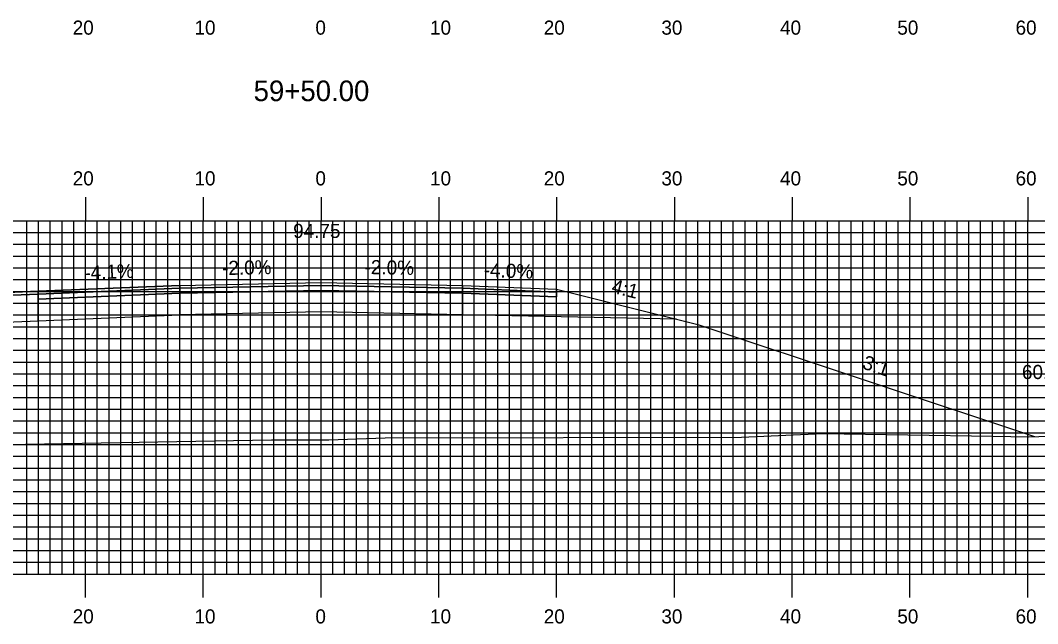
# Model space of a CAD drawing. Extents: x 1757462 to 1757806, y 442591 to 442811.
# Drawn here: x 1757602.6 to 1757689, y 442649.4 to 442700.7 of the extents above; entities that cross this region are included whole.
import ezdxf

# ---------------------------------------------------------------- set-up
doc = ezdxf.new("R2010")
doc.units = 0
for name, color, linetype in [('ANNOTATION', 7, 'Continuous'), ('D_Roadway_Centerline', 7, 'Continuous'), ('D_Roadway_Centerline_Text', 7, 'Continuous'), ('D_Roadway_Edge_Shoulder', 7, 'Continuous'), ('D_Roadway_Edge_TW', 7, 'Continuous'), ('D_Roadway_Pavement', 7, 'Continuous'), ('D_Roadway_SlopeLines', 7, 'Continuous'), ('D_Roadway_SubGrade', 7, 'Continuous'), ('D_Text_Standard', 7, 'Continuous'), ('H_V ANNOTATION', 7, 'Continuous'), ('MAJOR', 7, 'Continuous'), ('MINOR', 7, 'Continuous'), ('S_Roadway_Centerline', 7, 'Continuous')]:
    doc.layers.add(name, color=color, linetype=linetype)

msp = doc.modelspace()

# ---------------------------------------------------------------- linework, layer by layer
at = {"layer": 'D_Roadway_Centerline'}
msp.add_lwpolyline([(1757553.341, 442664.105), (1757577.567, 442672.184), (1757584.046, 442674.345), (1757584.056, 442674.348), (1757584.094, 442674.357), (1757595.268, 442677.152), (1757596.094, 442677.358), (1757604.094, 442677.678), (1757616.109, 442678.177), (1757628.109, 442678.417), (1757640.109, 442678.177), (1757648.109, 442677.857), (1757658.283, 442675.313), (1757660.109, 442674.857), (1757688.68, 442665.333)], dxfattribs=at)
at = {"layer": 'D_Roadway_Edge_Shoulder'}
for points in [[(1757604.094, 442677.678), (1757596.094, 442677.358), (1757596.094, 442677.108), (1757604.094, 442677.428)], [(1757640.109, 442678.177), (1757648.109, 442677.857), (1757648.109, 442677.607), (1757640.109, 442677.927)]]:
    msp.add_lwpolyline(points, close=True, dxfattribs=at)
at = {"layer": 'D_Roadway_Edge_TW'}
for points in [[(1757616.109, 442678.177), (1757604.094, 442677.678), (1757604.094, 442677.428), (1757616.109, 442677.927)], [(1757616.109, 442677.927), (1757616.109, 442678.177), (1757628.109, 442678.417), (1757640.109, 442678.177), (1757640.109, 442677.927), (1757628.109, 442678.167)]]:
    msp.add_lwpolyline(points, close=True, dxfattribs=at)
msp.add_lwpolyline([(1757616.109, 442678.177), (1757616.109, 442677.927)], dxfattribs=at)
at = {"layer": 'D_Roadway_Pavement'}
for points in [[(1757616.109, 442677.927), (1757604.094, 442677.428), (1757604.094, 442677.012), (1757616.109, 442677.51)], [(1757616.109, 442677.51), (1757616.109, 442677.927), (1757628.109, 442678.167), (1757640.109, 442677.927), (1757640.109, 442677.51), (1757628.109, 442677.75)], [(1757640.109, 442677.927), (1757648.109, 442677.607), (1757648.109, 442677.19), (1757640.109, 442677.51)]]:
    msp.add_lwpolyline(points, close=True, dxfattribs=at)
for points in [[(1757616.109, 442677.927), (1757616.109, 442677.51)], [(1757616.109, 442677.927), (1757616.109, 442677.51)], [(1757604.094, 442677.428), (1757604.094, 442677.012)]]:
    msp.add_lwpolyline(points, dxfattribs=at)
at = {"layer": 'D_Roadway_SlopeLines'}
msp.add_lwpolyline([(1757648.109, 442677.857), (1757660.109, 442674.857), (1757688.68, 442665.333)], dxfattribs=at)
at = {"layer": 'D_Roadway_SubGrade'}
for points in [[(1757616.109, 442675.677), (1757616.109, 442677.51), (1757628.109, 442677.75), (1757640.109, 442677.51), (1757640.109, 442675.677), (1757628.109, 442675.917)], [(1757640.109, 442677.51), (1757648.109, 442677.19), (1757648.109, 442677.607), (1757648.109, 442677.857), (1757658.283, 442675.313), (1757640.109, 442675.677)], [(1757604.094, 442677.012), (1757604.094, 442677.428), (1757596.094, 442677.108), (1757596.094, 442677.358), (1757584.046, 442674.345), (1757604.094, 442675.178)], [(1757616.109, 442677.51), (1757604.094, 442677.012), (1757604.094, 442675.178), (1757616.109, 442675.677)]]:
    msp.add_lwpolyline(points, close=True, dxfattribs=at)
msp.add_lwpolyline([(1757616.109, 442677.51), (1757616.109, 442675.677)], dxfattribs=at)
at = {"layer": 'MAJOR'}
for p, q in [((1757608.109, 442685.669), (1757608.109, 442683.665)), ((1757618.109, 442685.669), (1757618.109, 442683.665)), ((1757628.109, 442685.669), (1757628.109, 442683.665)), ((1757638.109, 442685.669), (1757638.109, 442683.665)), ((1757648.109, 442685.669), (1757648.109, 442683.665)), ((1757658.109, 442685.669), (1757658.109, 442683.665)), ((1757668.109, 442685.669), (1757668.109, 442683.665)), ((1757678.109, 442685.669), (1757678.109, 442683.665)), ((1757688.109, 442685.669), (1757688.109, 442683.665)), ((1757488.109, 442683.665), (1757768.109, 442683.665)), ((1757488.109, 442683.665), (1757768.109, 442683.665)), ((1757608.109, 442653.665), (1757608.109, 442683.665)), ((1757618.109, 442653.665), (1757618.109, 442683.665)), ((1757628.109, 442653.665), (1757628.109, 442683.665)), ((1757638.109, 442653.665), (1757638.109, 442683.665)), ((1757648.109, 442653.665), (1757648.109, 442683.665)), ((1757658.109, 442653.665), (1757658.109, 442683.665)), ((1757668.109, 442653.665), (1757668.109, 442683.665)), ((1757678.109, 442653.665), (1757678.109, 442683.665)), ((1757688.109, 442653.665), (1757688.109, 442683.665)), ((1757488.109, 442678.665), (1757768.109, 442678.665)), ((1757488.109, 442673.665), (1757768.109, 442673.665)), ((1757488.109, 442668.665), (1757768.109, 442668.665)), ((1757488.109, 442663.665), (1757768.109, 442663.665)), ((1757488.109, 442658.665), (1757768.109, 442658.665)), ((1757488.109, 442653.665), (1757768.109, 442653.665)), ((1757488.109, 442653.665), (1757768.109, 442653.665)), ((1757608.109, 442651.661), (1757608.109, 442653.665)), ((1757618.109, 442651.661), (1757618.109, 442653.665)), ((1757628.109, 442651.661), (1757628.109, 442653.665)), ((1757638.109, 442651.661), (1757638.109, 442653.665)), ((1757648.109, 442651.661), (1757648.109, 442653.665)), ((1757658.109, 442651.661), (1757658.109, 442653.665)), ((1757668.109, 442651.661), (1757668.109, 442653.665)), ((1757678.109, 442651.661), (1757678.109, 442653.665)), ((1757688.109, 442651.661), (1757688.109, 442653.665))]:
    msp.add_line(p, q, dxfattribs=at)
at = {"layer": 'MINOR'}
for p, q in [((1757603.109, 442653.665), (1757603.109, 442683.665)), ((1757604.109, 442653.665), (1757604.109, 442683.665)), ((1757605.109, 442653.665), (1757605.109, 442683.665)), ((1757606.109, 442653.665), (1757606.109, 442683.665)), ((1757607.109, 442653.665), (1757607.109, 442683.665)), ((1757609.109, 442653.665), (1757609.109, 442683.665)), ((1757610.109, 442653.665), (1757610.109, 442683.665)), ((1757611.109, 442653.665), (1757611.109, 442683.665)), ((1757612.109, 442653.665), (1757612.109, 442683.665)), ((1757613.109, 442653.665), (1757613.109, 442683.665)), ((1757614.109, 442653.665), (1757614.109, 442683.665)), ((1757615.109, 442653.665), (1757615.109, 442683.665)), ((1757616.109, 442653.665), (1757616.109, 442683.665)), ((1757617.109, 442653.665), (1757617.109, 442683.665)), ((1757619.109, 442653.665), (1757619.109, 442683.665)), ((1757620.109, 442653.665), (1757620.109, 442683.665)), ((1757621.109, 442653.665), (1757621.109, 442683.665)), ((1757622.109, 442653.665), (1757622.109, 442683.665)), ((1757623.109, 442653.665), (1757623.109, 442683.665)), ((1757624.109, 442653.665), (1757624.109, 442683.665)), ((1757625.109, 442653.665), (1757625.109, 442683.665)), ((1757626.109, 442653.665), (1757626.109, 442683.665)), ((1757627.109, 442653.665), (1757627.109, 442683.665)), ((1757629.109, 442653.665), (1757629.109, 442683.665)), ((1757630.109, 442653.665), (1757630.109, 442683.665)), ((1757631.109, 442653.665), (1757631.109, 442683.665)), ((1757632.109, 442653.665), (1757632.109, 442683.665)), ((1757633.109, 442653.665), (1757633.109, 442683.665)), ((1757634.109, 442653.665), (1757634.109, 442683.665)), ((1757635.109, 442653.665), (1757635.109, 442683.665)), ((1757636.109, 442653.665), (1757636.109, 442683.665)), ((1757637.109, 442653.665), (1757637.109, 442683.665)), ((1757639.109, 442653.665), (1757639.109, 442683.665)), ((1757640.109, 442653.665), (1757640.109, 442683.665)), ((1757641.109, 442653.665), (1757641.109, 442683.665)), ((1757642.109, 442653.665), (1757642.109, 442683.665)), ((1757643.109, 442653.665), (1757643.109, 442683.665)), ((1757644.109, 442653.665), (1757644.109, 442683.665)), ((1757645.109, 442653.665), (1757645.109, 442683.665)), ((1757646.109, 442653.665), (1757646.109, 442683.665)), ((1757647.109, 442653.665), (1757647.109, 442683.665)), ((1757649.109, 442653.665), (1757649.109, 442683.665)), ((1757650.109, 442653.665), (1757650.109, 442683.665)), ((1757651.109, 442653.665), (1757651.109, 442683.665)), ((1757652.109, 442653.665), (1757652.109, 442683.665)), ((1757653.109, 442653.665), (1757653.109, 442683.665)), ((1757654.109, 442653.665), (1757654.109, 442683.665)), ((1757655.109, 442653.665), (1757655.109, 442683.665)), ((1757656.109, 442653.665), (1757656.109, 442683.665)), ((1757657.109, 442653.665), (1757657.109, 442683.665)), ((1757659.109, 442653.665), (1757659.109, 442683.665)), ((1757660.109, 442653.665), (1757660.109, 442683.665)), ((1757661.109, 442653.665), (1757661.109, 442683.665)), ((1757662.109, 442653.665), (1757662.109, 442683.665)), ((1757663.109, 442653.665), (1757663.109, 442683.665)), ((1757664.109, 442653.665), (1757664.109, 442683.665)), ((1757665.109, 442653.665), (1757665.109, 442683.665)), ((1757666.109, 442653.665), (1757666.109, 442683.665)), ((1757667.109, 442653.665), (1757667.109, 442683.665)), ((1757669.109, 442653.665), (1757669.109, 442683.665)), ((1757670.109, 442653.665), (1757670.109, 442683.665)), ((1757671.109, 442653.665), (1757671.109, 442683.665)), ((1757672.109, 442653.665), (1757672.109, 442683.665)), ((1757673.109, 442653.665), (1757673.109, 442683.665)), ((1757674.109, 442653.665), (1757674.109, 442683.665)), ((1757675.109, 442653.665), (1757675.109, 442683.665)), ((1757676.109, 442653.665), (1757676.109, 442683.665)), ((1757677.109, 442653.665), (1757677.109, 442683.665)), ((1757679.109, 442653.665), (1757679.109, 442683.665)), ((1757680.109, 442653.665), (1757680.109, 442683.665)), ((1757681.109, 442653.665), (1757681.109, 442683.665)), ((1757682.109, 442653.665), (1757682.109, 442683.665)), ((1757683.109, 442653.665), (1757683.109, 442683.665)), ((1757684.109, 442653.665), (1757684.109, 442683.665)), ((1757685.109, 442653.665), (1757685.109, 442683.665)), ((1757686.109, 442653.665), (1757686.109, 442683.665)), ((1757687.109, 442653.665), (1757687.109, 442683.665)), ((1757488.109, 442682.665), (1757768.109, 442682.665)), ((1757488.109, 442681.665), (1757768.109, 442681.665)), ((1757488.109, 442680.665), (1757768.109, 442680.665)), ((1757488.109, 442679.665), (1757768.109, 442679.665)), ((1757488.109, 442677.665), (1757768.109, 442677.665)), ((1757488.109, 442676.665), (1757768.109, 442676.665)), ((1757488.109, 442675.665), (1757768.109, 442675.665)), ((1757488.109, 442674.665), (1757768.109, 442674.665)), ((1757488.109, 442672.665), (1757768.109, 442672.665)), ((1757488.109, 442671.665), (1757768.109, 442671.665)), ((1757488.109, 442670.665), (1757768.109, 442670.665)), ((1757488.109, 442669.665), (1757768.109, 442669.665)), ((1757488.109, 442667.665), (1757768.109, 442667.665)), ((1757488.109, 442666.665), (1757768.109, 442666.665)), ((1757488.109, 442665.665), (1757768.109, 442665.665)), ((1757488.109, 442664.665), (1757768.109, 442664.665)), ((1757488.109, 442662.665), (1757768.109, 442662.665)), ((1757488.109, 442661.665), (1757768.109, 442661.665)), ((1757488.109, 442660.665), (1757768.109, 442660.665)), ((1757488.109, 442659.665), (1757768.109, 442659.665)), ((1757488.109, 442657.665), (1757768.109, 442657.665)), ((1757488.109, 442656.665), (1757768.109, 442656.665)), ((1757488.109, 442655.665), (1757768.109, 442655.665)), ((1757488.109, 442654.665), (1757768.109, 442654.665))]:
    msp.add_line(p, q, dxfattribs=at)
at = {"layer": 'S_Roadway_Centerline'}
msp.add_lwpolyline([(1757488.109, 442663.533), (1757499.205, 442663.855), (1757499.477, 442663.857), (1757499.832, 442663.849), (1757508.301, 442663.607), (1757541.719, 442663.795), (1757560.058, 442664.284), (1757582.586, 442664.419), (1757590.13, 442664.451), (1757623.89, 442665.047), (1757628.777, 442665.069), (1757633.54, 442665.217), (1757663.804, 442665.294), (1757670.706, 442665.59), (1757685.162, 442665.374), (1757688.209, 442665.318), (1757699.07, 442665.671)], dxfattribs=at)

# ---------------------------------------------------------------- texts
at = {"layer": 'ANNOTATION'}
for s, rotation, p in [('-2.0%', 1.14576, (1757619.715, 442679.049)), ('-2.0%', 358.85424, (1757631.795, 442679.143)), ('-4.1%', 2.37428, (1757608.03, 442678.643)), ('-4.0%', 357.70939, (1757641.901, 442678.907)), ('4:1', 345.96376, (1757652.702, 442677.57)), ('3:1', 341.56522, (1757673.998, 442671.135))]:
    msp.add_text(s, height=1.2, rotation=rotation, dxfattribs=at).set_placement(p)
at = {"layer": 'D_Roadway_Centerline'}
for s, p in [('C', (1757628.104, 442678.417)), ('L', (1757628.109, 442678.409))]:
    msp.add_text(s, height=0.0146, dxfattribs=at).set_placement(p)
at = {"layer": 'D_Roadway_Centerline_Text'}
msp.add_text('94.75', height=1.2, dxfattribs=at).set_placement((1757625.739, 442682.202))
at = {"layer": 'D_Text_Standard'}
msp.add_text("60.6'", height=1.2, dxfattribs=at).set_placement((1757687.624, 442670.22))
at = {"layer": 'H_V ANNOTATION'}
for s, height, p in [('20', 1.2, (1757607.017, 442699.465)), ('10', 1.2, (1757617.36, 442699.465)), ('0', 1.2, (1757627.627, 442699.465)), ('10', 1.2, (1757637.36, 442699.465)), ('20', 1.2, (1757647.017, 442699.465)), ('30', 1.2, (1757657.006, 442699.465)), ('40', 1.2, (1757667.081, 442699.465)), ('50', 1.2, (1757677.038, 442699.465)), ('60', 1.2, (1757687.081, 442699.465)), ('59+50.00', 1.75, (1757622.381, 442693.821)), ('20', 1.2, (1757607.017, 442686.665)), ('10', 1.2, (1757617.36, 442686.665)), ('0', 1.2, (1757627.627, 442686.665)), ('10', 1.2, (1757637.36, 442686.665)), ('20', 1.2, (1757647.017, 442686.665)), ('30', 1.2, (1757657.006, 442686.665)), ('40', 1.2, (1757667.081, 442686.665)), ('50', 1.2, (1757677.038, 442686.665)), ('60', 1.2, (1757687.081, 442686.665)), ('20', 1.2, (1757607.017, 442649.465)), ('10', 1.2, (1757617.36, 442649.465)), ('0', 1.2, (1757627.627, 442649.465)), ('10', 1.2, (1757637.36, 442649.465)), ('20', 1.2, (1757647.017, 442649.465)), ('30', 1.2, (1757657.006, 442649.465)), ('40', 1.2, (1757667.081, 442649.465)), ('50', 1.2, (1757677.038, 442649.465)), ('60', 1.2, (1757687.081, 442649.465))]:
    msp.add_text(s, height=height, dxfattribs=at).set_placement(p)

doc.saveas('drawing.dxf')
